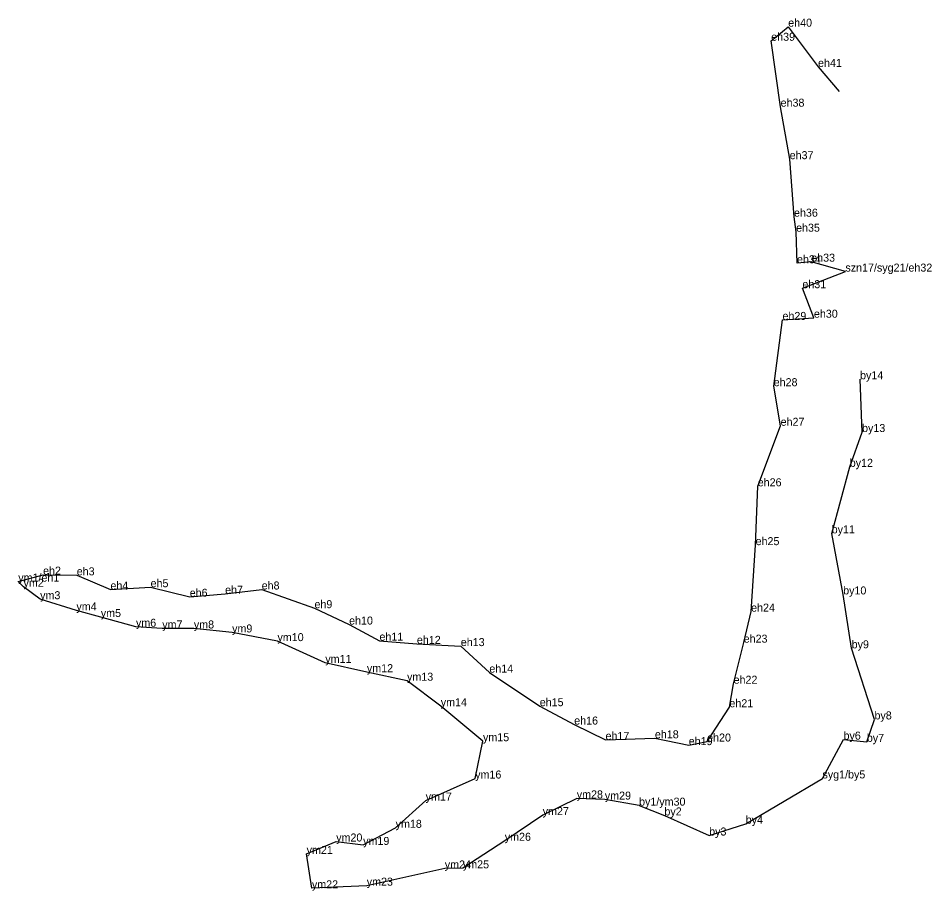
# Model space of a CAD drawing. Extents: x 2072529 to 2267990, y 436423 to 470008.
# Drawn here: x 2238515 to 2239200, y 438660 to 439314 of the extents above; entities that cross this region are included whole.
import ezdxf

# ---------------------------------------------------------------- set-up
doc = ezdxf.new("R2010")
doc.units = 0
doc.layers.add('Level 3', color=7, linetype='Continuous')
doc.layers.add('Old_Level_52', color=7, linetype='Continuous')

msp = doc.modelspace()

# ---------------------------------------------------------------- linework, layer by layer
at = {"layer": 'Level 3'}
for p, q in [((2239091.979, 439308.072), (2239091.979, 439308.072)), ((2239079.237, 439297.515), (2239079.237, 439297.515)), ((2239114.329, 439277.877), (2239114.329, 439277.877)), ((2239086.284, 439248.095), (2239086.284, 439248.095)), ((2239093.071, 439208.732), (2239093.071, 439208.732)), ((2239096.326, 439165.592), (2239096.326, 439165.592)), ((2239097.892, 439154.342), (2239097.892, 439154.342)), ((2239109.215, 439131.846), (2239109.215, 439131.846)), ((2239098.577, 439130.699), (2239098.577, 439130.699)), ((2239134.834, 439124.43), (2239134.834, 439124.43)), ((2239102.615, 439111.994), (2239102.615, 439111.994)), ((2239087.678, 439088.185), (2239087.678, 439088.185)), ((2239111.249, 439089.843), (2239111.249, 439089.843)), ((2239145.841, 439043.717), (2239145.841, 439043.717)), ((2239081.088, 439038.495), (2239081.088, 439038.495)), ((2239086.286, 439008.825), (2239086.286, 439008.825)), ((2239147.326, 439004.132), (2239147.326, 439004.132)), ((2239138.109, 438978.03), (2239138.109, 438978.03)), ((2239069.117, 438963.428), (2239069.117, 438963.428)), ((2239124.567, 438928.139), (2239124.567, 438928.139)), ((2239067.523, 438919.3), (2239067.523, 438919.3)), ((2238514.817, 438892), (2238514.817, 438892)), ((2238533.402, 438897.166), (2238533.402, 438897.166)), ((2238558.63, 438896.676), (2238558.63, 438896.676)), ((2238518.733, 438888.078), (2238518.733, 438888.078)), ((2238583.886, 438885.987), (2238583.886, 438885.987)), ((2238613.995, 438887.75), (2238613.995, 438887.75)), ((2238697.275, 438886.049), (2238697.275, 438886.049)), ((2238531.219, 438878.765), (2238531.219, 438878.765)), ((2238643.324, 438880.621), (2238643.324, 438880.621)), ((2238669.871, 438882.818), (2238669.871, 438882.818)), ((2239133.152, 438882.352), (2239133.152, 438882.352)), ((2238736.841, 438872.026), (2238736.841, 438872.026)), ((2238558.405, 438870.316), (2238558.405, 438870.316)), ((2238576.684, 438865.427), (2238576.684, 438865.427)), ((2239064.165, 438869.457), (2239064.165, 438869.457)), ((2238603.028, 438858.119), (2238603.028, 438858.119)), ((2238762.809, 438859.755), (2238762.809, 438859.755)), ((2238622.743, 438856.846), (2238622.743, 438856.846)), ((2238646.439, 438856.823), (2238646.439, 438856.823)), ((2238675.12, 438853.835), (2238675.12, 438853.835)), ((2238709.113, 438847.322), (2238709.113, 438847.322)), ((2238785.578, 438847.668), (2238785.578, 438847.668)), ((2238813.636, 438845.281), (2238813.636, 438845.281)), ((2238846.553, 438843.617), (2238846.553, 438843.617)), ((2239058.605, 438846.183), (2239058.605, 438846.183)), ((2239139.536, 438841.96), (2239139.536, 438841.96)), ((2238744.982, 438830.99), (2238744.982, 438830.99)), ((2238776.157, 438824.055), (2238776.157, 438824.055)), ((2238867.946, 438823.732), (2238867.946, 438823.732)), ((2238806.248, 438817.648), (2238806.248, 438817.648)), ((2239051.032, 438815.388), (2239051.032, 438815.388)), ((2238831.539, 438798.555), (2238831.539, 438798.555)), ((2238905.742, 438798.56), (2238905.742, 438798.56)), ((2239047.877, 438797.757), (2239047.877, 438797.757)), ((2238931.564, 438784.78), (2238931.564, 438784.78)), ((2239156.644, 438788.622), (2239156.644, 438788.622)), ((2238863.177, 438772.303), (2238863.177, 438772.303)), ((2238955.041, 438773.269), (2238955.041, 438773.269)), ((2238992.044, 438774.463), (2238992.044, 438774.463)), ((2239017.396, 438769.349), (2239017.396, 438769.349)), ((2239031.197, 438772.048), (2239031.197, 438772.048)), ((2239133.423, 438773.468), (2239133.423, 438773.468)), ((2239150.91, 438771.79), (2239150.91, 438771.79)), ((2238857.315, 438744.302), (2238857.315, 438744.302)), ((2239117.662, 438744.384), (2239117.662, 438744.384)), ((2238820.208, 438727.817), (2238820.208, 438727.817)), ((2238933.477, 438729.421), (2238933.477, 438729.421)), ((2238954.505, 438728.5), (2238954.505, 438728.5)), ((2238980.174, 438723.985), (2238980.174, 438723.985)), ((2238907.938, 438716.845), (2238907.938, 438716.845)), ((2238999.167, 438716.603), (2238999.167, 438716.603)), ((2238797.692, 438707.339), (2238797.692, 438707.339)), ((2239060.14, 438710.417), (2239060.14, 438710.417)), ((2239032.711, 438701.562), (2239032.711, 438701.562)), ((2238753.135, 438697.08), (2238753.135, 438697.08)), ((2238773.368, 438694.505), (2238773.368, 438694.505)), ((2238879.502, 438697.622), (2238879.502, 438697.622)), ((2238730.977, 438687.747), (2238730.977, 438687.747)), ((2238834.56, 438676.88), (2238834.56, 438676.88)), ((2238848.107, 438676.973), (2238848.107, 438676.973)), ((2238734.936, 438661.975), (2238734.936, 438661.975)), ((2238776.041, 438663.965), (2238776.041, 438663.965))]:
    msp.add_line(p, q, dxfattribs=at)
at = {"layer": 'Old_Level_52'}
for points in [[(2238980.174, 438723.985), (2238954.505, 438728.5), (2238933.477, 438729.421), (2238907.938, 438716.845), (2238879.502, 438697.622), (2238848.107, 438676.973), (2238834.56, 438676.88), (2238776.041, 438663.965), (2238734.936, 438661.975), (2238730.977, 438687.747), (2238753.135, 438697.08), (2238773.368, 438694.505), (2238797.692, 438707.339), (2238820.208, 438727.817), (2238857.315, 438744.302), (2238863.177, 438772.303), (2238831.539, 438798.555), (2238806.248, 438817.648), (2238776.157, 438824.055), (2238744.982, 438830.99), (2238709.113, 438847.322), (2238675.12, 438853.835), (2238646.439, 438856.823), (2238622.743, 438856.846), (2238603.028, 438858.119), (2238576.684, 438865.427), (2238558.405, 438870.316), (2238531.219, 438878.765), (2238518.733, 438888.078), (2238514.817, 438892), (2238533.402, 438897.166), (2238558.63, 438896.676), (2238583.886, 438885.987), (2238613.995, 438887.75), (2238643.324, 438880.621), (2238669.871, 438882.818), (2238697.275, 438886.049), (2238736.841, 438872.026), (2238762.809, 438859.755), (2238785.578, 438847.668), (2238813.636, 438845.281), (2238846.553, 438843.617), (2238867.946, 438823.732), (2238905.742, 438798.56), (2238931.564, 438784.78), (2238955.041, 438773.269), (2238992.044, 438774.463), (2239017.396, 438769.349), (2239031.197, 438772.048), (2239047.877, 438797.757), (2239051.032, 438815.388), (2239058.605, 438846.183), (2239064.165, 438869.457), (2239067.523, 438919.3), (2239069.117, 438963.428), (2239086.286, 439008.825), (2239081.088, 439038.495), (2239087.678, 439088.185), (2239111.249, 439089.843), (2239102.615, 439111.994), (2239134.834, 439124.43), (2239109.215, 439131.846), (2239098.577, 439130.699), (2239097.892, 439154.342), (2239096.326, 439165.592), (2239093.071, 439208.732), (2239086.284, 439248.095), (2239079.237, 439297.515), (2239091.979, 439308.072), (2239114.329, 439277.877), (2239130.096, 439259.513)], [(2238980.174, 438723.985), (2238999.167, 438716.603), (2239032.711, 438701.562), (2239060.14, 438710.417), (2239117.662, 438744.384), (2239133.423, 438773.468), (2239150.91, 438771.79), (2239156.644, 438788.622), (2239139.536, 438841.96), (2239133.152, 438882.352), (2239124.567, 438928.139), (2239138.109, 438978.03), (2239147.326, 439004.132), (2239145.841, 439043.717)]]:
    msp.add_lwpolyline(points, dxfattribs=at)

# ---------------------------------------------------------------- texts
for s, p in [('eh40', (2239091.979, 439308.072)), ('eh39', (2239079.237, 439297.515)), ('eh41', (2239114.329, 439277.877)), ('eh38', (2239086.284, 439248.095)), ('eh37', (2239093.071, 439208.732)), ('eh36', (2239096.326, 439165.592)), ('eh35', (2239097.892, 439154.342)), ('eh33', (2239109.215, 439131.846)), ('eh34', (2239098.577, 439130.699)), ('szn17/syg21/eh32', (2239134.834, 439124.43)), ('eh31', (2239102.615, 439111.994)), ('eh29', (2239087.678, 439088.185)), ('eh30', (2239111.249, 439089.843)), ('by14', (2239145.841, 439043.717)), ('eh28', (2239081.088, 439038.495)), ('eh27', (2239086.286, 439008.825)), ('by13', (2239147.326, 439004.132)), ('by12', (2239138.109, 438978.03)), ('eh26', (2239069.117, 438963.428)), ('by11', (2239124.567, 438928.139)), ('eh25', (2239067.523, 438919.3)), ('eh2', (2238533.402, 438897.166)), ('eh3', (2238558.63, 438896.676)), ('ym1/eh1', (2238514.817, 438892)), ('ym2', (2238518.733, 438888.078)), ('eh4', (2238583.886, 438885.987)), ('eh5', (2238613.995, 438887.75)), ('eh8', (2238697.275, 438886.049)), ('ym3', (2238531.219, 438878.765)), ('eh6', (2238643.324, 438880.621)), ('eh7', (2238669.871, 438882.818)), ('by10', (2239133.152, 438882.352)), ('eh9', (2238736.841, 438872.026)), ('ym4', (2238558.405, 438870.316)), ('ym5', (2238576.684, 438865.427)), ('eh24', (2239064.165, 438869.457)), ('ym6', (2238603.028, 438858.119)), ('eh10', (2238762.809, 438859.755)), ('ym7', (2238622.743, 438856.846)), ('ym8', (2238646.439, 438856.823)), ('ym9', (2238675.12, 438853.835)), ('ym10', (2238709.113, 438847.322)), ('eh11', (2238785.578, 438847.668)), ('eh12', (2238813.636, 438845.281)), ('eh23', (2239058.605, 438846.183)), ('eh13', (2238846.553, 438843.617)), ('by9', (2239139.536, 438841.96)), ('ym11', (2238744.982, 438830.99)), ('ym12', (2238776.157, 438824.055)), ('eh14', (2238867.946, 438823.732)), ('ym13', (2238806.248, 438817.648)), ('eh22', (2239051.032, 438815.388)), ('ym14', (2238831.539, 438798.555)), ('eh15', (2238905.742, 438798.56)), ('eh21', (2239047.877, 438797.757)), ('eh16', (2238931.564, 438784.78)), ('by8', (2239156.644, 438788.622)), ('ym15', (2238863.177, 438772.303)), ('eh17', (2238955.041, 438773.269)), ('eh18', (2238992.044, 438774.463)), ('eh19', (2239017.396, 438769.349)), ('eh20', (2239031.197, 438772.048)), ('by6', (2239133.423, 438773.468)), ('by7', (2239150.91, 438771.79)), ('ym16', (2238857.315, 438744.302)), ('syg1/by5', (2239117.662, 438744.384)), ('ym28', (2238933.477, 438729.421)), ('ym29', (2238954.505, 438728.5)), ('ym17', (2238820.208, 438727.817)), ('by1/ym30', (2238980.174, 438723.985)), ('ym27', (2238907.938, 438716.845)), ('by2', (2238999.167, 438716.603)), ('by4', (2239060.14, 438710.417)), ('ym18', (2238797.692, 438707.339)), ('by3', (2239032.711, 438701.562)), ('ym20', (2238753.135, 438697.08)), ('ym19', (2238773.368, 438694.505)), ('ym26', (2238879.502, 438697.622)), ('ym21', (2238730.977, 438687.747)), ('ym24', (2238834.56, 438676.88)), ('ym25', (2238848.107, 438676.973)), ('ym22', (2238734.936, 438661.975)), ('ym23', (2238776.041, 438663.965))]:
    msp.add_text(s, height=6).set_placement(p)

doc.saveas('drawing.dxf')
